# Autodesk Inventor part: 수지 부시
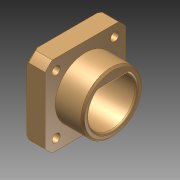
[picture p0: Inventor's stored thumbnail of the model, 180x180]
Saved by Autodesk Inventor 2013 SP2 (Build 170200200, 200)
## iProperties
Created: 2024-11
Part Number: 수지 부시
Material: Generic
Document SubType Name: Modeling
Designer: a
Density: 1 g/cm^3
Author: a
변환 표준: STEP AP214IS
전처리기: Build: 200, Release: 2013 SP2 Update 6 - Date: Thu 07/17/2014
전송 단위: 밀리미터
불확실성: 0.01
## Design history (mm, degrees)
node "수지 부시1"
node "솔리드1"
node "기준1"
